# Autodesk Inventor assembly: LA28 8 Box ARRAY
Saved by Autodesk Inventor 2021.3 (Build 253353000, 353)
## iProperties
Created: 2023-01
Part Number: LA28 8 Box ARRAY
Document SubType Name: Assembly
Designer: AdminForWorker
Title: LA28 8 Box ARRAY v2
Author: AdminForWorker
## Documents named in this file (3)
- c:\worker\convert-fusion-r08-cosv3\tmp\job-1\7\output\files\be2e730f-f331-4d02-b9c8-0db6989d2b3d\da10ee65-0c70-41f0-b9f5-a12f13a5bb2b.iam
- c:\worker\convert-fusion-r08-cosv3\tmp\job-1\7\output\files\be2e730f-f331-4d02-b9c8-0db6989d2b3d\LA28 RF1 Sheet Metal Assembly v3.iam
- c:\worker\convert-fusion-r08-cosv3\tmp\job-1\7\output\files\be2e730f-f331-4d02-b9c8-0db6989d2b3d\LA28 TOUR BLOCK v2.ipt
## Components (9 placed, 2 different names)
1. LA28 RF1 Sheet Metal Assembly v3:1 [sub-assembly]
2. LA28 TOUR BLOCK v2:1
3. LA28 TOUR BLOCK v2:2
4. LA28 TOUR BLOCK v2:3
5. LA28 TOUR BLOCK v2:4
6. LA28 TOUR BLOCK v2:5
7. LA28 TOUR BLOCK v2:6
8. LA28 TOUR BLOCK v2:7
9. LA28 TOUR BLOCK v2:8
